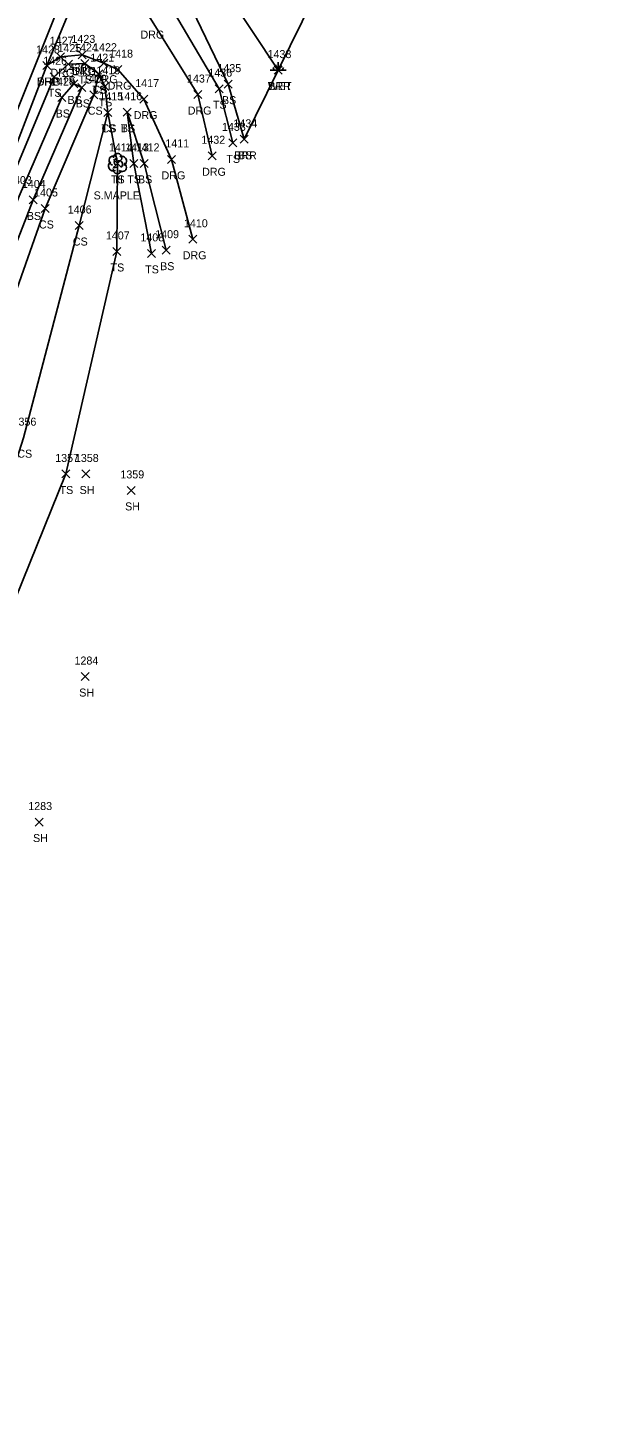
# Model space of a CAD drawing. Extents: x 1554917 to 1555870, y 813367 to 816333.
# Drawn here: x 1555192.9 to 1555336, y 813586.9 to 813931.9 of the extents above; entities that cross this region are included whole.
import ezdxf

# ---------------------------------------------------------------- set-up
doc = ezdxf.new("R2010")
doc.units = 0
for name, color, linetype in [('L_A', 7, 'Continuous'), ('L_C', 7, 'Continuous'), ('L_I', 7, 'Continuous'), ('L_TIC', 7, 'Continuous'), ('LABL', 7, 'Continuous'), ('LELB', 7, 'Continuous'), ('LTD', 7, 'Continuous'), ('LWET', 7, 'Continuous'), ('P_A', 7, 'Continuous'), ('P_I', 7, 'Continuous'), ('P_TIC', 7, 'Continuous'), ('PET', 7, 'Continuous'), ('PSP', 7, 'Continuous'), ('R_A', 7, 'Continuous'), ('R_I', 7, 'Continuous'), ('R_TIC', 7, 'Continuous'), ('RDG', 7, 'Continuous')]:
    doc.layers.add(name, color=color, linetype=linetype)

msp = doc.modelspace()

# ---------------------------------------------------------------- linework, layer by layer
at = {"layer": 'L_TIC'}
for points in [[(1555202.03, 813921.76), (1555204.03, 813923.76)], [(1555204.03, 813921.76), (1555202.03, 813923.76)], [(1555206.16, 813921.92), (1555208.16, 813923.92)], [(1555208.16, 813921.92), (1555206.16, 813923.92)], [(1555198.5, 813918.6), (1555200.5, 813920.6)], [(1555200.5, 813918.6), (1555198.5, 813920.6)], [(1555198.5, 813918.6), (1555200.5, 813920.6)], [(1555200.5, 813918.6), (1555198.5, 813920.6)], [(1555209.66, 813919.37), (1555211.66, 813921.37)], [(1555211.66, 813919.37), (1555209.66, 813921.37)], [(1555209.66, 813919.37), (1555211.66, 813921.37)], [(1555211.66, 813919.37), (1555209.66, 813921.37)], [(1555254.51, 813920.27), (1555256.51, 813922.27)], [(1555256.51, 813920.27), (1555254.51, 813922.27)], [(1555203.39, 813916.83), (1555205.39, 813918.83)], [(1555205.39, 813916.83), (1555203.39, 813918.83)], [(1555205.44, 813915.94), (1555207.44, 813917.94)], [(1555207.44, 813915.94), (1555205.44, 813917.94)], [(1555205.44, 813915.94), (1555207.44, 813917.94)], [(1555207.44, 813915.94), (1555205.44, 813917.94)], [(1555211.19, 813916.21), (1555213.19, 813918.21)], [(1555213.19, 813916.21), (1555211.19, 813918.21)], [(1555239.76, 813915.62), (1555241.76, 813917.62)], [(1555241.76, 813915.62), (1555239.76, 813917.62)], [(1555241.99, 813916.76), (1555243.99, 813918.76)], [(1555243.99, 813916.76), (1555241.99, 813918.76)], [(1555200.42, 813913.42), (1555202.42, 813915.42)], [(1555202.42, 813913.42), (1555200.42, 813915.42)], [(1555208.44, 813914.13), (1555210.44, 813916.13)], [(1555210.44, 813914.13), (1555208.44, 813916.13)], [(1555211.9, 813909.7), (1555213.9, 813911.7)], [(1555213.9, 813909.7), (1555211.9, 813911.7)], [(1555211.9, 813909.7), (1555213.9, 813911.7)], [(1555213.9, 813909.7), (1555211.9, 813911.7)], [(1555216.72, 813909.74), (1555218.72, 813911.74)], [(1555218.72, 813909.74), (1555216.72, 813911.74)], [(1555216.72, 813909.74), (1555218.72, 813911.74)], [(1555218.72, 813909.74), (1555216.72, 813911.74)], [(1555243.11, 813902.09), (1555245.11, 813904.09)], [(1555245.11, 813902.09), (1555243.11, 813904.09)], [(1555245.98, 813902.97), (1555247.98, 813904.97)], [(1555247.98, 813902.97), (1555245.98, 813904.97)], [(1555245.98, 813902.97), (1555247.98, 813904.97)], [(1555247.98, 813902.97), (1555245.98, 813904.97)], [(1555214.28, 813896.96), (1555216.28, 813898.96)], [(1555216.28, 813896.96), (1555214.28, 813898.96)], [(1555218.36, 813896.97), (1555220.36, 813898.97)], [(1555220.36, 813896.97), (1555218.36, 813898.97)], [(1555221, 813896.96), (1555223, 813898.96)], [(1555223, 813896.96), (1555221, 813898.96)], [(1555193.21, 813887.82), (1555195.21, 813889.82)], [(1555195.21, 813887.82), (1555193.21, 813889.82)], [(1555196.25, 813885.69), (1555198.25, 813887.69)], [(1555198.25, 813885.69), (1555196.25, 813887.69)], [(1555204.71, 813881.43), (1555206.71, 813883.43)], [(1555206.71, 813881.43), (1555204.71, 813883.43)], [(1555214.18, 813874.95), (1555216.18, 813876.95)], [(1555216.18, 813874.95), (1555214.18, 813876.95)], [(1555222.82, 813874.47), (1555224.82, 813876.47)], [(1555224.82, 813874.47), (1555222.82, 813876.47)], [(1555226.52, 813875.27), (1555228.52, 813877.27)], [(1555228.52, 813875.27), (1555226.52, 813877.27)], [(1555201.44, 813819.35), (1555203.44, 813821.35)], [(1555203.44, 813819.35), (1555201.44, 813821.35)], [(1555206.37, 813819.35), (1555208.37, 813821.35)], [(1555208.37, 813819.35), (1555206.37, 813821.35)], [(1555217.74, 813815.24), (1555219.74, 813817.24)], [(1555219.74, 813815.24), (1555217.74, 813817.24)], [(1555206.26, 813768.73), (1555208.26, 813770.73)], [(1555208.26, 813768.73), (1555206.26, 813770.73)], [(1555194.71, 813732.37), (1555196.71, 813734.37)], [(1555196.71, 813732.37), (1555194.71, 813734.37)]]:
    msp.add_lwpolyline(points, dxfattribs=at)
at = {"layer": 'LABL'}
msp.add_lwpolyline([(1555246.98, 813903.97), (1555255.51, 813921.27), (1555270.42, 813951.6), (1555277.93, 813973.79), (1555289.33, 813994.04), (1555300.33, 814008.73), (1555305.54, 814022.92), (1555313.64, 814041.1), (1555318.32, 814081.03), (1555326.1, 814100.25), (1555336, 814125.43)], dxfattribs=at)
at = {"layer": 'LELB'}
for points in [[(1555244.11, 813903.09), (1555240.76, 813916.62), (1555228.48, 813937.37), (1555217.61, 813950.51), (1555215.58, 813954.88), (1555216.99, 813960.62), (1555222.34, 813976.41), (1555235.01, 814010.77), (1555239.56, 814017.88), (1555245.78, 814033.09), (1555255.18, 814058.98), (1555268.47, 814094.07), (1555274.97, 814112.22), (1555278.17, 814116.24), (1555282.02, 814117.52), (1555286.39, 814116.11), (1555289.99, 814109.88), (1555296.54, 814106.47), (1555313.61, 814126.36), (1555333.57, 814137.64)], [(1555246.98, 813903.97), (1555242.99, 813917.76), (1555232.88, 813938.62), (1555220.79, 813951), (1555219.56, 813956.1), (1555223.47, 813959.89), (1555224.61, 813963.07), (1555227.33, 813969.39), (1555236.62, 813985.65), (1555248.53, 814008.06), (1555259.52, 814030.52), (1555254.85, 814031.94), (1555258, 814033.78), (1555265.85, 814057.48), (1555276.22, 814093.19), (1555280.35, 814112.31), (1555282.12, 814115.72), (1555282.41, 814111.98), (1555282.34, 814108.27)], [(1555091.02, 813589.64), (1555093.93, 813609.08), (1555110.01, 813657.36), (1555123.68, 813699.33), (1555136.3, 813730.66), (1555163.02, 813794.74), (1555179.29, 813835.95), (1555197.25, 813886.69), (1555209.44, 813915.13), (1555210.66, 813920.37)], [(1555101.22, 813603.84), (1555111.95, 813631.93), (1555127.97, 813651.43), (1555152.02, 813699.54), (1555162.91, 813721.01), (1555173.86, 813750.23), (1555186.14, 813780.13), (1555202.44, 813820.35), (1555215.18, 813875.95), (1555215.28, 813897.96), (1555212.9, 813910.7), (1555212.19, 813917.21), (1555210.66, 813920.37), (1555207.16, 813922.92), (1555203.03, 813922.76), (1555199.5, 813919.6)], [(1554992.4, 813377.01), (1555009.62, 813423.34), (1555030.72, 813482.86), (1555047.7, 813528.1), (1555056, 813550.42), (1555062.05, 813566.99), (1555080.33, 813615.57), (1555099.41, 813662.25), (1555114.13, 813700.62), (1555127, 813733.84), (1555152.94, 813799.24), (1555168.16, 813840.25), (1555187.47, 813890.8), (1555199.5, 813919.6)], [(1554997.34, 813375.96), (1555001.03, 813380.2), (1555008.26, 813399.3), (1555016.85, 813422.36), (1555039.01, 813478.41), (1555055.21, 813525.71), (1555062.73, 813548.53), (1555066.84, 813564.4), (1555085.89, 813613.91), (1555101.8, 813661.36), (1555117.2, 813700.9), (1555129.69, 813732.82), (1555155.55, 813797.61), (1555171.4, 813838.65), (1555190.74, 813889.78), (1555201.42, 813914.42), (1555204.39, 813917.83), (1555206.44, 813916.94)], [(1555060.32, 813524.58), (1555067.83, 813537.87), (1555070.43, 813550.96), (1555072.05, 813560.86), (1555087.88, 813613.15), (1555106.35, 813658.95), (1555120.2, 813700.04), (1555133.19, 813731.1), (1555158.65, 813797.07), (1555174.38, 813837.99), (1555194.21, 813888.82), (1555206.44, 813916.94)], [(1555111.95, 813631.93), (1555123.2, 813652.42), (1555137.56, 813696.49), (1555156.74, 813743.02), (1555177.49, 813784.47), (1555191.84, 813829.42), (1555205.71, 813882.43), (1555212.9, 813910.7)], [(1555223.82, 813875.47), (1555219.36, 813897.97), (1555217.72, 813910.74)], [(1555227.52, 813876.27), (1555222, 813897.96), (1555217.72, 813910.74)]]:
    msp.add_lwpolyline(points, dxfattribs=at)
at = {"layer": 'LTD'}
msp.add_line((1555215.28, 813897.96), (1555215.28, 813897.96), dxfattribs=at)
msp.add_line((1555215.28, 813897.96), (1555215.28, 813897.96), dxfattribs=at)
msp.add_arc((1555215.33, 813899.4), 1.05, 335.5272, 180.9563, dxfattribs=at)
for centre, major_axis, ratio, start_param, end_param in [((1555214.49, 813898.63), (1.21, -0.51), 0.895232, 1.570796, 4.712389), ((1555215.07, 813898.42), (-0.208, -0.792), 0.645439, 3.141593, 6.283185), ((1555216.32, 813898.55), (-1.14, -0.48), 0.949671, 1.570796, 4.712389), ((1555214.2, 813897.26), (0.58, -1.04), 0.959034, 3.141593, 6.283185), ((1555215.28, 813896.46), (0.26, 1.06), 0.942809, 1.570796, 4.712389), ((1555214.82, 813897.21), (-0.625, -0.083), 0.423636, 0, 3.141593), ((1555215.78, 813897.8), (-0.5, 0.667), 0.989748, 3.141593, 6.283185), ((1555216.28, 813897.13), (-1.09, 0.79), 0.841452, 1.570796, 4.712389)]:
    msp.add_ellipse(centre, major_axis=major_axis, ratio=ratio, start_param=start_param, end_param=end_param, dxfattribs=at)
at = {"layer": 'LWET'}
for p, q in [((1555257.51, 813921.27), (1555253.51, 813921.27)), ((1555254.51, 813921.27), (1555254.18, 813921.94)), ((1555255.51, 813921.27), (1555254.84, 813922.61)), ((1555255.51, 813921.27), (1555255.51, 813923.27)), ((1555255.51, 813921.27), (1555256.18, 813922.61)), ((1555256.51, 813921.27), (1555256.84, 813921.94))]:
    msp.add_line(p, q, dxfattribs=at)
msp.add_lwpolyline([(1555255.51, 813921.27), (1555242.27, 813941.15), (1555224.61, 813963.07)], dxfattribs=at)
at = {"layer": 'P_TIC'}
for points in [[(1555196.67, 813921.42), (1555198.67, 813923.42)], [(1555198.67, 813921.42), (1555196.67, 813923.42)]]:
    msp.add_lwpolyline(points, dxfattribs=at)
at = {"layer": 'PET'}
msp.add_lwpolyline([(1554987.55, 813378.28), (1555004.34, 813425.43), (1555025.15, 813482.53), (1555042.33, 813529.78), (1555057.09, 813568.35), (1555075.57, 813617.35), (1555093.79, 813663.7), (1555108.49, 813702.81), (1555121.71, 813736.27), (1555147.41, 813801.52), (1555163.02, 813841.94), (1555182.57, 813892.25), (1555203.7, 813945.01)], dxfattribs=at)
at = {"layer": 'PSP'}
msp.add_lwpolyline([(1554990.52, 813377.71), (1555007.26, 813424.1), (1555027.97, 813481.79), (1555045.41, 813528.93), (1555059.94, 813567), (1555096.82, 813663.08), (1555111.75, 813701.59), (1555124.82, 813734.75), (1555150.26, 813800.36), (1555166.19, 813840.91), (1555185.69, 813891.41), (1555197.67, 813922.42), (1555211.91, 813956.86)], dxfattribs=at)
at = {"layer": 'R_TIC'}
for points in [[(1555200.07, 813923.62), (1555202.07, 813925.62)], [(1555202.07, 813923.62), (1555200.07, 813925.62)], [(1555205.51, 813924.06), (1555207.51, 813926.06)], [(1555207.51, 813924.06), (1555205.51, 813926.06)], [(1555210.91, 813921.99), (1555212.91, 813923.99)], [(1555212.91, 813921.99), (1555210.91, 813923.99)], [(1555196.67, 813921.42), (1555198.67, 813923.42)], [(1555198.67, 813921.42), (1555196.67, 813923.42)], [(1555214.37, 813920.39), (1555216.37, 813922.39)], [(1555216.37, 813920.39), (1555214.37, 813922.39)], [(1555220.88, 813913.01), (1555222.88, 813915.01)], [(1555222.88, 813913.01), (1555220.88, 813915.01)], [(1555234.38, 813914.16), (1555236.38, 813916.16)], [(1555236.38, 813914.16), (1555234.38, 813916.16)], [(1555227.83, 813897.96), (1555229.83, 813899.96)], [(1555229.83, 813897.96), (1555227.83, 813899.96)], [(1555237.98, 813898.86), (1555239.98, 813900.86)], [(1555239.98, 813898.86), (1555237.98, 813900.86)], [(1555233.13, 813878), (1555235.13, 813880)], [(1555235.13, 813878), (1555233.13, 813880)]]:
    msp.add_lwpolyline(points, dxfattribs=at)
at = {"layer": 'RDG'}
for points in [[(1555238.98, 813899.86), (1555235.38, 813915.16), (1555223.57, 813934.14), (1555215.77, 813943.97), (1555212.97, 813951.71), (1555211.91, 813956.86)], [(1555234.13, 813879), (1555228.83, 813898.96), (1555221.88, 813914.01), (1555215.37, 813921.39), (1555211.91, 813922.99), (1555206.51, 813925.06), (1555201.07, 813924.62), (1555197.67, 813922.42)]]:
    msp.add_lwpolyline(points, dxfattribs=at)

# ---------------------------------------------------------------- texts
at = {"layer": 'L_A'}
for s, p in [('TS', (1555197.91, 813914.6)), ('TS', (1555197.91, 813914.6)), ('TS', (1555201.44, 813917.76)), ('TS', (1555205.57, 813917.92)), ('TS', (1555209.07, 813915.37)), ('CS', (1555209.1, 813915.37)), ('WET', (1555252.89, 813916.27)), ('BRR', (1555253, 813916.27)), ('BS', (1555202.83, 813912.83)), ('BS', (1555204.88, 813911.94)), ('BS', (1555204.88, 813911.94)), ('TS', (1555210.6, 813912.21)), ('TS', (1555239.17, 813911.62)), ('BS', (1555241.43, 813912.76)), ('BS', (1555199.86, 813909.42)), ('CS', (1555207.88, 813910.13)), ('TS', (1555211.31, 813905.7)), ('CS', (1555211.34, 813905.7)), ('TS', (1555216.13, 813905.74)), ('BS', (1555216.17, 813905.74)), ('TS', (1555242.52, 813898.09)), ('BRR', (1555244.47, 813898.97)), ('BS', (1555245.42, 813898.97)), ('TS', (1555213.69, 813892.96)), ('H', (1555214.72, 813892.96)), ('TS', (1555217.77, 813892.97)), ('BS', (1555220.44, 813892.96)), ('BS', (1555192.65, 813883.82)), ('CS', (1555195.69, 813881.69)), ('CS', (1555204.16, 813877.43)), ('TS', (1555213.59, 813870.95)), ('TS', (1555222.23, 813870.47)), ('BS', (1555225.96, 813871.27)), ('CS', (1555190.28, 813824.42)), ('TS', (1555200.85, 813815.35)), ('SH', (1555205.85, 813815.35)), ('SH', (1555217.23, 813811.24)), ('SH', (1555205.75, 813764.73)), ('SH', (1555194.2, 813728.37))]:
    msp.add_text(s, height=2, dxfattribs=at).set_placement(p)
at = {"layer": 'L_C'}
msp.add_text('S.MAPLE', height=2, dxfattribs=at).set_placement((1555209.35, 813888.96))
at = {"layer": 'L_I'}
for s, p in [('1425', (1555200.34, 813925.76)), ('1424', (1555204.46, 813925.92)), ('1426', (1555196.76, 813922.6)), ('1426', (1555196.76, 813922.6)), ('1421', (1555208.53, 813923.37)), ('1421', (1555208.53, 813923.37)), ('1438', (1555252.82, 813924.27)), ('1438', (1555252.82, 813924.27)), ('1430', (1555201.61, 813920.83)), ('1431', (1555204.31, 813919.94)), ('1431', (1555204.31, 813919.94)), ('1420', (1555206.66, 813918.13)), ('1419', (1555210.06, 813920.21)), ('1436', (1555238.02, 813919.62)), ('1435', (1555240.29, 813920.76)), ('1429', (1555198.72, 813917.42)), ('1415', (1555210.77, 813913.7)), ('1415', (1555210.77, 813913.7)), ('1416', (1555215.54, 813913.74)), ('1416', (1555215.54, 813913.74)), ('1433', (1555241.42, 813906.09)), ('1434', (1555244.29, 813906.97)), ('1434', (1555244.29, 813906.97)), ('1414', (1555213.16, 813900.96)), ('1414', (1555213.16, 813900.96)), ('1413', (1555217.23, 813900.97)), ('1412', (1555219.87, 813900.96)), ('1403', (1555187.96, 813892.78)), ('1404', (1555191.43, 813891.82)), ('1405', (1555194.48, 813889.69)), ('1406', (1555202.89, 813885.43)), ('1407', (1555212.41, 813878.95)), ('1408', (1555221.05, 813878.47)), ('1409', (1555224.74, 813879.27)), ('1356', (1555189.09, 813832.42)), ('1357', (1555199.75, 813823.35)), ('1358', (1555204.67, 813823.35)), ('1359', (1555216.04, 813819.24)), ('1284', (1555204.57, 813772.73)), ('1283', (1555193.02, 813736.37))]:
    msp.add_text(s, height=2, dxfattribs=at).set_placement(p)
at = {"layer": 'P_A'}
msp.add_text('SHP', height=2, dxfattribs=at).set_placement((1555195.21, 813917.42))
at = {"layer": 'P_I'}
msp.add_text('1428', height=2, dxfattribs=at).set_placement((1555194.98, 813925.42))
at = {"layer": 'R_A'}
for p in [(1555221.06, 813929.14), (1555198.56, 813919.62), (1555203.99, 813920.06), (1555209.4, 813917.99), (1555195.16, 813917.42), (1555212.86, 813916.39), (1555219.37, 813909.01), (1555232.87, 813910.16), (1555226.32, 813893.96), (1555236.46, 813894.86), (1555231.62, 813874)]:
    msp.add_text('DRG', height=2, dxfattribs=at).set_placement(p)
at = {"layer": 'R_I'}
for s, p in [('1428', (1555194.98, 813925.42)), ('1427', (1555198.38, 813927.62)), ('1423', (1555203.81, 813928.06)), ('1422', (1555209.22, 813925.99)), ('1418', (1555213.24, 813924.39)), ('1437', (1555232.69, 813918.16)), ('1417', (1555219.76, 813917.01)), ('1411', (1555227.27, 813901.96)), ('1432', (1555236.28, 813902.86)), ('1410', (1555231.92, 813882))]:
    msp.add_text(s, height=2, dxfattribs=at).set_placement(p)

doc.saveas('drawing.dxf')
